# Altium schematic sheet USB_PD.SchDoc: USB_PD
size A4; SheetNumber: 8; SheetTotal: 10
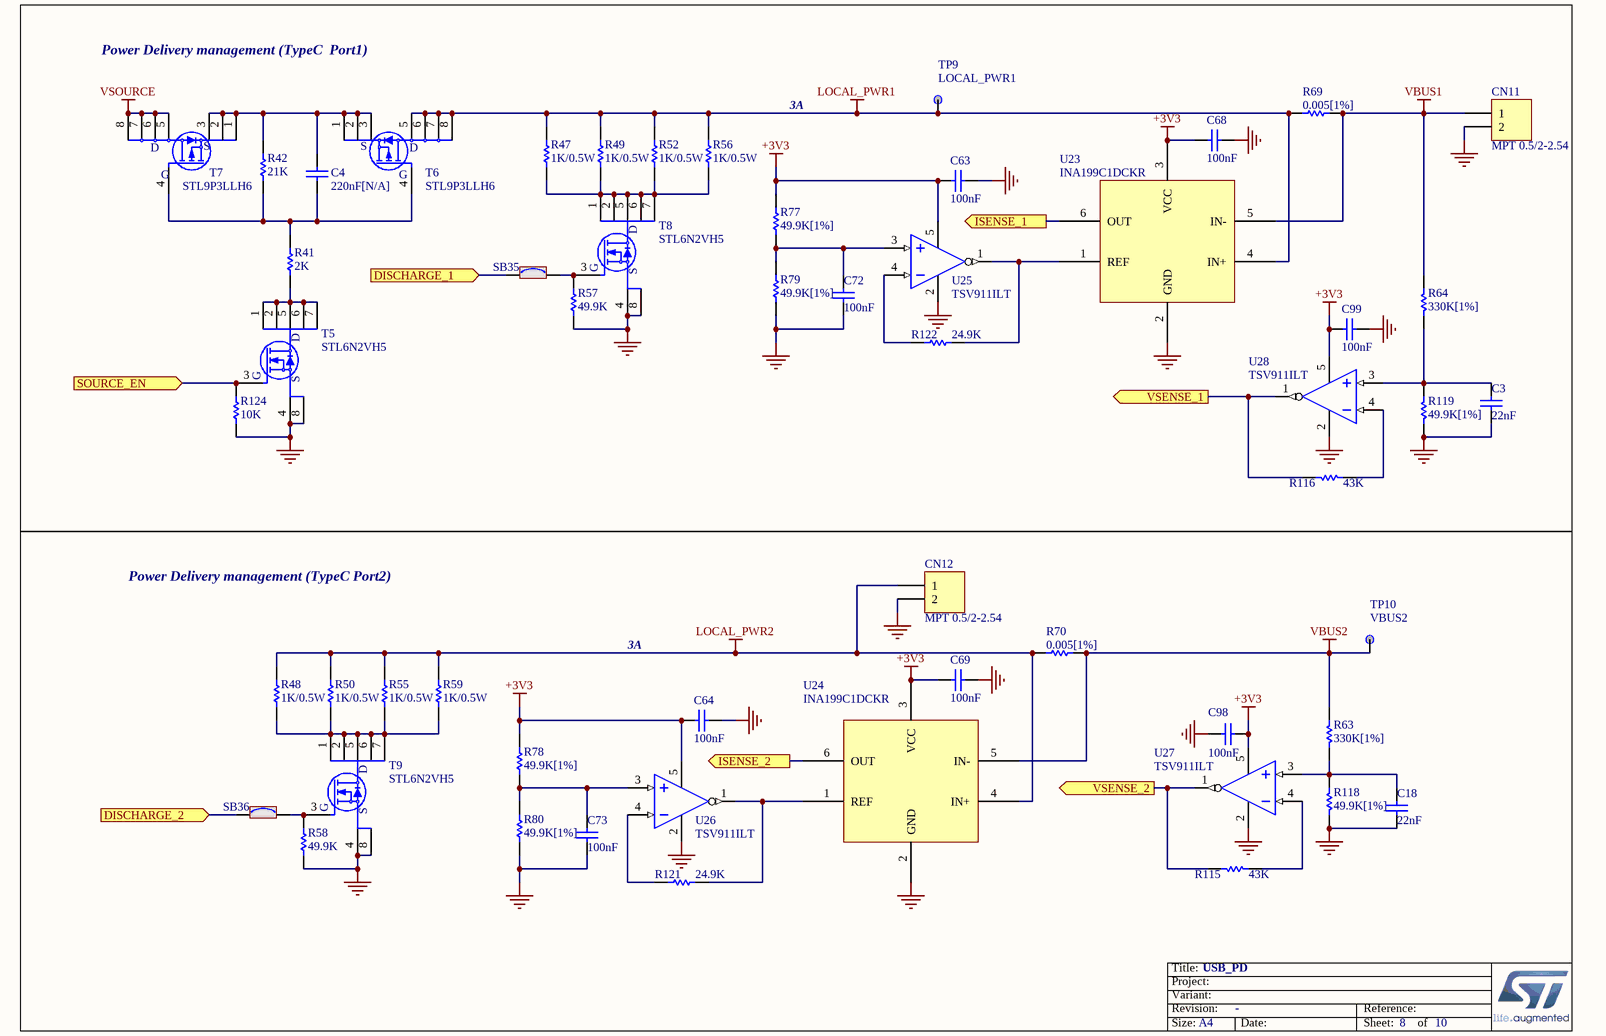
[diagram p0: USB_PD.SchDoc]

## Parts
C3  22nF  [0603C]
C4  220nF[N/A]  [0603C]
C18  22nF  [0603C]
C63  100nF  [0603C]
C64  100nF  [0603C]
C68  100nF  [0603C]
C69  100nF  [0603C]
C72  100nF  [0603C]
C73  100nF  [0603C]
C98  100nF  [0603C]
C99  100nF  [0603C]
CN11  MPT 0.5/2-2.54  [PHOENIX_1725656]
CN12  MPT 0.5/2-2.54  [PHOENIX_1725656]
R41  2K  [0603R]
R42  21K  [0603R]
R47  1K/0.5W  [1210R]
R48  1K/0.5W  [1210R]
R49  1K/0.5W  [1210R]
R50  1K/0.5W  [1210R]
R52  1K/0.5W  [1210R]
R55  1K/0.5W  [1210R]
R56  1K/0.5W  [1210R]
R57  49.9K  [0603R]
R58  49.9K  [0603R]
R59  1K/0.5W  [1210R]
R63  330K[1%]  [0603R]
R64  330K[1%]  [0603R]
R69  0.005[1%]  [2512R]
R70  0.005[1%]  [2512R]
R77  49.9K[1%]  [0603R]
R78  49.9K[1%]  [0603R]
R79  49.9K[1%]  [0603R]
R80  49.9K[1%]  [0603R]
R115  43K  [0603R]
R116  43K  [0603R]
R118  49.9K[1%]  [0603R]
R119  49.9K[1%]  [0603R]
R121  24.9K  [0603R]
R122  24.9K  [0603R]
R124  10K  [0603R]
SB35  Solder Bridge ON  [SB_0603]  (value not drawn)
SB36  Solder Bridge ON  [SB_0603]  (value not drawn)
T5  STL6N2VH5  [DFN6_0R65_2X2_2TP_C]
T6  STL9P3LLH6  [SOIC8_MOS_S]
T7  STL9P3LLH6  [SOIC8_MOS_S]
T8  STL6N2VH5  [DFN6_0R65_2X2_2TP_C]
T9  STL6N2VH5  [DFN6_0R65_2X2_2TP_C]
TP9  LOCAL_PWR1  [TP]
TP10  VBUS2  [TP]
U23  INA199C1DCKR  [SC70-6]
U24  INA199C1DCKR  [SC70-6]
U25  TSV911ILT  [SOT23-5]
U26  TSV911ILT  [SOT23-5]
U27  TSV911ILT  [SOT23-5]
U28  TSV911ILT  [SOT23-5]

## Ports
DISCHARGE_1 (in), DISCHARGE_2 (in), ISENSE_1 (out), ISENSE_2 (out), SOURCE_EN (in), VSENSE_1 (out), VSENSE_2 (out)

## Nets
+3V3: C63.1 C64.1 C68.1 C69.1 C98.1 C99.1 R77.2 R78.2 U23.3(VCC) U24.3(VCC) U25.5(VCC) U26.5(VCC) U27.5(VCC) U28.5(VCC)
GND: C3.2 C18.2 C63.2 C64.2 C68.2 C69.2 C72.2 C73.2 C98.2 C99.2 CN11.2 CN12.2 R57.1 R58.1 R79.1 R80.1 R118.1 R119.1 R124.1 T5.4(S) T5.8(S) T8.4(S) T8.8(S) T9.4(S) T9.8(S) U23.2(GND) U24.2(GND) U25.2(GND) U26.2(GND) U27.2(GND) U28.2(GND)
LOCAL_PWR1: R47.1 R49.1 R52.1 R56.1 R69.1 T6.5(D) T6.6(D) T6.7(D) T6.8(D) TP9.1 U23.4(IN+)
LOCAL_PWR2: CN12.1 R48.1 R50.1 R55.1 R59.1 R70.1 U24.4(IN+)
VBUS1: CN11.1 R64.2 R69.2 U23.5(IN-)
VBUS2: R63.2 R70.2 TP10.1 U24.5(IN-)
VSOURCE: T7.5(D) T7.6(D) T7.7(D) T7.8(D)
DISCHARGE_1: SB35.1 ; port DISCHARGE_1
DISCHARGE_2: SB36.1 ; port DISCHARGE_2
ISENSE_1: U23.6(OUT) ; port ISENSE_1
ISENSE_2: U24.6(OUT) ; port ISENSE_2
SOURCE_EN: R124.2 T5.3(G) ; port SOURCE_EN
VSENSE_1: R116.1 U28.1(NC) ; port VSENSE_1
VSENSE_2: R115.1 U27.1(NC) ; port VSENSE_2
NetC3_1: C3.1 R64.1 R119.2 U28.3(IN+)
NetC4_1: C4.1 R42.2 T6.1(S) T6.2(S) T6.3(S) T7.1(S) T7.2(S) T7.3(S)
NetC4_2: C4.2 R41.2 R42.1 T6.4(G) T7.4(G)
NetC18_1: C18.1 R63.1 R118.2 U27.3(IN+)
NetC72_1: C72.1 R77.1 R79.2 U25.3(IN+)
NetC73_1: C73.1 R78.1 R80.2 U26.3(IN+)
NetR41_1: R41.1 T5.1(D) T5.2(D) T5.5(D) T5.6(D) T5.7(D)
NetR47_2: R47.2 R49.2 R52.2 R56.2 T8.1(D) T8.2(D) T8.5(D) T8.6(D) T8.7(D)
NetR48_2: R48.2 R50.2 R55.2 R59.2 T9.1(D) T9.2(D) T9.5(D) T9.6(D) T9.7(D)
NetR57_2: R57.2 SB35.2 T8.3(G)
NetR58_2: R58.2 SB36.2 T9.3(G)
NetR115_2: R115.2 U27.4(IN-)
NetR116_2: R116.2 U28.4(IN-)
NetR121_1: R121.1 U24.1(REF) U26.1(NC)
NetR121_2: R121.2 U26.4(IN-)
NetR122_1: R122.1 U23.1(REF) U25.1(NC)
NetR122_2: R122.2 U25.4(IN-)

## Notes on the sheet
- Power Delivery management (TypeC  Port1)
- 3A
- Power Delivery management (TypeC Port2)

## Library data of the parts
C3 C18 C63 C64 C68 C69 C72 C73 C98 C99 = Cap: Capacitor; Value: 10nF
C4 = CAP: Capacitor; Value: 100nF
CN11 CN12 = Screw-connector
R41 R42 R47-R50 R52 R55-R59 R63 R64 R77-R80 R115 R116 R118 R119 R121 R122 R124 = res1: Resistor; Value: 1K
R69 R70 = ERJM1WSF5M0U: Resistor; Value: 1K
SB35 SB36 = SB_ON: Fitted: YES; Ordered by: Subcon
TP9 TP10 = TP
U25-U28 = TSV911ILT: Ordered by: Subcon; ECCN_US/EU: EAR99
